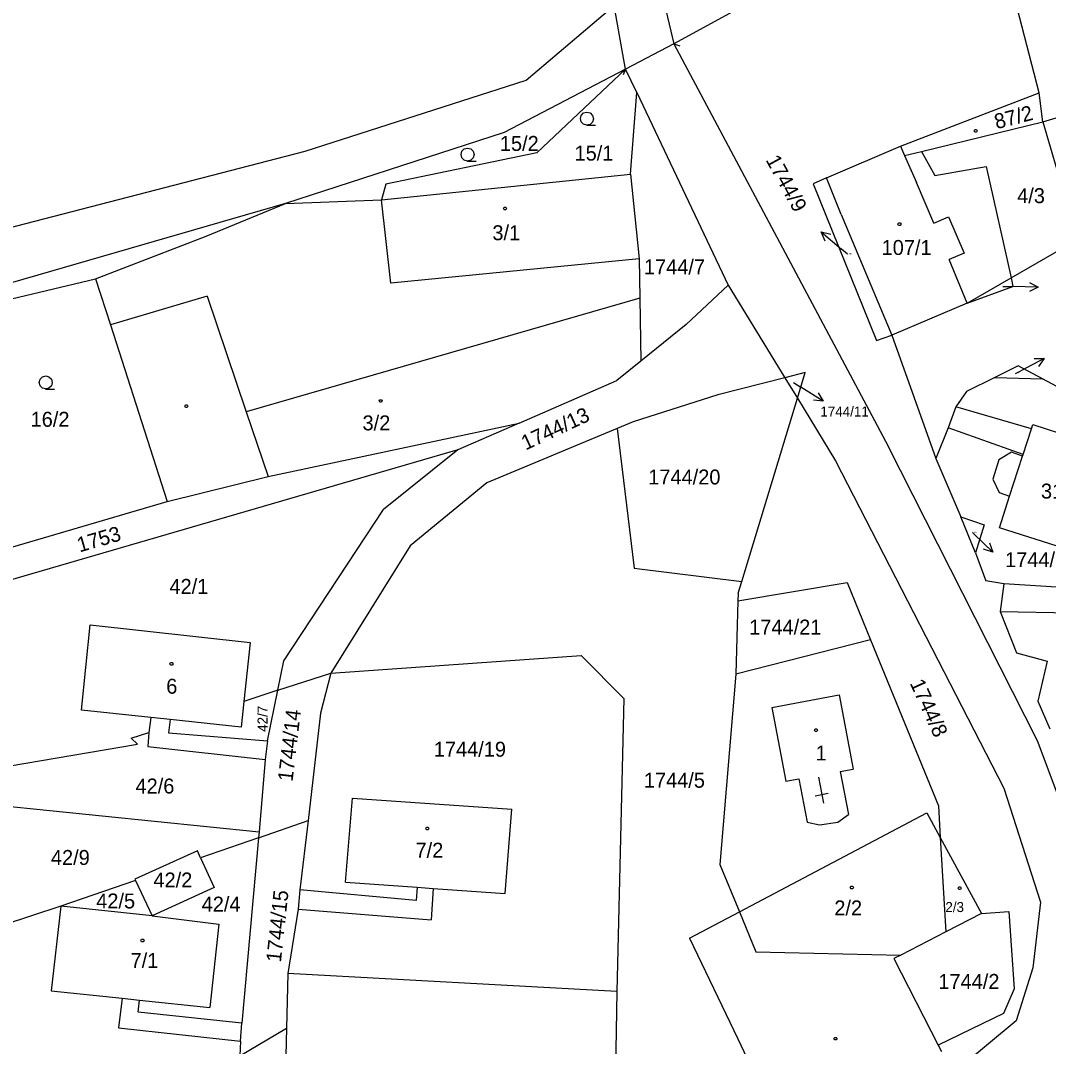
# Model space of a CAD drawing. Extents: x -799786 to -795190, y -1021716 to -1017834.
# Drawn here: x -798047.9 to -797930.9, y -1019053.9 to -1018937.1 of the extents above; entities that cross this region are included whole.
import ezdxf

# ---------------------------------------------------------------- set-up
doc = ezdxf.new("R2010")
doc.units = 0
for name, color, linetype in [('Default', 7, 'Continuous'), ('KN_HRANICE', 7, 'Continuous'), ('KN_KULTURY', 7, 'Continuous'), ('KN_PARCELY', 7, 'Continuous'), ('KN_SLUCKY', 7, 'Continuous')]:
    doc.layers.add(name, color=color, linetype=linetype)

# ---------------------------------------------------------------- blocks, each defined once
blk = doc.blocks.new('304')
at = {"layer": 'Default'}
blk.add_lwpolyline([(0, 0), (-0.38, 0.1), (-0.65, 0.37), (-0.75, 0.74), (-0.65, 1.11), (-0.38, 1.38), (-0.01, 1.48), (0.36, 1.38), (0.63, 1.11), (0.73, 0.73), (0.63, 0.35), (0.36, 0.08), (-0.02, -0.02), (0.98, -0.02)], dxfattribs=at)
blk = doc.blocks.new('NAHRADNI_SYMBOL')
at = {"layer": 'Default'}
blk.add_lwpolyline([(0.09, 0.15), (0.18, 0), (0.09, -0.15), (-0.09, -0.15), (-0.18, 0), (-0.09, 0.15), (0.09, 0.15)], dxfattribs=at)
blk = doc.blocks.new('10292')
at = {"layer": 'Default'}
blk.add_line((0, 3), (0, 0), dxfattribs=at)
blk.add_lwpolyline([(-0.5, 2), (0, 3), (0.5, 2)], dxfattribs=at)
blk = doc.blocks.new('402')
at = {"layer": 'Default'}
blk.add_lwpolyline([(0.09, 0.15), (0.18, 0), (0.09, -0.15), (-0.09, -0.15), (-0.18, 0), (-0.09, 0.15), (0.09, 0.15)], dxfattribs=at)
blk = doc.blocks.new('4091')
at = {"layer": 'Default'}
for p, q in [((0, 0), (0, 3)), ((0.75, 2), (-0.75, 2))]:
    blk.add_line(p, q, dxfattribs=at)
blk = doc.blocks.new('4201')
at = {"layer": 'Default'}
blk.add_line((0, 0), (-0.5, -0.5), dxfattribs=at)

msp = doc.modelspace()

# ---------------------------------------------------------------- linework, layer by layer
at = {"layer": 'KN_HRANICE'}
for p, q in [((-797931.93, -1018945.35), (-797936.24, -1018928.69)), ((-797959.42, -1018932.05), (-797973.52, -1018939.78)), ((-797990.31, -1018943.91), (-797980.3, -1018935.41)), ((-797979.01, -1018942.65), (-797980.3, -1018935.41)), ((-797973.52, -1018939.78), (-797979.01, -1018942.65)), ((-797973.52, -1018939.78), (-797949.14, -1018985.55)), ((-797979.01, -1018942.65), (-797992.83, -1018949.87)), ((-797979.01, -1018942.65), (-797989.12, -1018952.16)), ((-797977.72, -1018945.29), (-797979.01, -1018942.65)), ((-798015.47, -1018951.99), (-797990.31, -1018943.91)), ((-797978.44, -1018954.61), (-797977.72, -1018945.29)), ((-797977.72, -1018945.29), (-797967.32, -1018967.21)), ((-797947.72, -1018951.42), (-797931.93, -1018945.35)), ((-797931.53, -1018948.65), (-797931.93, -1018945.35)), ((-797945.33, -1018952), (-797931.53, -1018948.65)), ((-797931.53, -1018948.65), (-797928.55, -1018958.72)), ((-797992.83, -1018949.87), (-798017.72, -1018957.95)), ((-797956.16, -1018955.02), (-797947.72, -1018951.42)), ((-797947.72, -1018951.42), (-797947.25, -1018952.46)), ((-798092.87, -1018972.02), (-798015.47, -1018951.99)), ((-797989.12, -1018952.16), (-798006.31, -1018955.72)), ((-797947.25, -1018952.46), (-797945.33, -1018952)), ((-797945.33, -1018952), (-797943.82, -1018954.73)), ((-797943.82, -1018954.73), (-797937.95, -1018953.73)), ((-797937.95, -1018953.73), (-797935.14, -1018966.41)), ((-798006.8, -1018957.51), (-797978.44, -1018954.61)), ((-797978.44, -1018954.61), (-797977.47, -1018964.22)), ((-797956.16, -1018955.02), (-797957.66, -1018955.7)), ((-797954.48, -1018959.19), (-797956.16, -1018955.02)), ((-798006.31, -1018955.72), (-798006.8, -1018957.51)), ((-797957.66, -1018955.7), (-797950.45, -1018973.51)), ((-798017.72, -1018957.95), (-798093.97, -1018979.94)), ((-798026.73, -1018961.66), (-798017.72, -1018957.95)), ((-798017.72, -1018957.95), (-798006.8, -1018957.51)), ((-797954.48, -1018959.19), (-797948.7, -1018972.9)), ((-798039.33, -1018966.51), (-798026.73, -1018961.66)), ((-797935.14, -1018966.41), (-797927.62, -1018962.07)), ((-797977.47, -1018964.22), (-797977.39, -1018968.72)), ((-798055.93, -1018970.44), (-798039.33, -1018966.51)), ((-798039.33, -1018966.51), (-798037.65, -1018971.74)), ((-797940.13, -1018969.29), (-797935.14, -1018966.41)), ((-797935.14, -1018966.41), (-797934.92, -1018967.39)), ((-797967.32, -1018967.21), (-797972.13, -1018971.71)), ((-797967.32, -1018967.21), (-797960.88, -1018977.77)), ((-797940.13, -1018969.29), (-797934.92, -1018967.39)), ((-797977.39, -1018968.72), (-798022.18, -1018981.64)), ((-797977.39, -1018968.72), (-797977.26, -1018975.87)), ((-797940.13, -1018969.29), (-797948.7, -1018972.9)), ((-798037.65, -1018971.74), (-798031.19, -1018991.85)), ((-797972.13, -1018971.71), (-797977.26, -1018975.87)), ((-797950.45, -1018973.51), (-797948.7, -1018972.9)), ((-797948.7, -1018972.9), (-797943.7, -1018986.95)), ((-797977.26, -1018975.87), (-797979.99, -1018978.08)), ((-797958.57, -1018977.18), (-797960.88, -1018977.77)), ((-797959.46, -1018980.1), (-797958.57, -1018977.18)), ((-797934.34, -1018976.4), (-797936.98, -1018977.73)), ((-797931.55, -1018977.89), (-797934.34, -1018976.4)), ((-797991.11, -1018982.92), (-797979.99, -1018978.08)), ((-797960.88, -1018977.77), (-797968.5, -1018979.72)), ((-797960.88, -1018977.77), (-797959.46, -1018980.1)), ((-797936.98, -1018977.73), (-797940.19, -1018979.34)), ((-797936.98, -1018977.73), (-797931.55, -1018977.89)), ((-797925.6, -1018981.08), (-797931.55, -1018977.89)), ((-797940.19, -1018979.34), (-797941.42, -1018981.08)), ((-797968.5, -1018979.72), (-797978.16, -1018982.8)), ((-797965.79, -1019000.95), (-797959.46, -1018980.1)), ((-797959.46, -1018980.1), (-797955.12, -1018987.21)), ((-798022.18, -1018981.64), (-798019.7, -1018989)), ((-797941.42, -1018981.08), (-797942.31, -1018983.45)), ((-797932.82, -1018983.58), (-797941.42, -1018981.08)), ((-798019.7, -1018989), (-797991.11, -1018982.92)), ((-797991.11, -1018982.92), (-797998.12, -1018985.97)), ((-797978.16, -1018982.8), (-797979.95, -1018983.55)), ((-797932.82, -1018983.58), (-797932.67, -1018983.1)), ((-797932.67, -1018983.1), (-797924.31, -1018985.78)), ((-797979.95, -1018983.55), (-797994.81, -1018989.72)), ((-797942.31, -1018983.45), (-797943.7, -1018986.95)), ((-797933.76, -1018986.48), (-797942.31, -1018983.45)), ((-797998.12, -1018985.97), (-798052.33, -1019001.73)), ((-797998.12, -1018985.97), (-798006.58, -1018992.76)), ((-797932.14, -1019019.09), (-797949.14, -1018985.55)), ((-797935.1, -1018986.25), (-797936.51, -1018987.12)), ((-797933.84, -1018986.67), (-797935.1, -1018986.25)), ((-797933.84, -1018986.67), (-797933.76, -1018986.48)), ((-797955.12, -1018987.21), (-797935.97, -1019024.47)), ((-797943.7, -1018986.95), (-797940.85, -1018993.6)), ((-797936.51, -1018987.12), (-797937.21, -1018989.3)), ((-798031.19, -1018991.85), (-798019.7, -1018989)), ((-797994.81, -1018989.72), (-798003.54, -1018996.9)), ((-797937.21, -1018989.3), (-797936.5, -1018990.81)), ((-797936.5, -1018990.81), (-797935.31, -1018991.23)), ((-797936.46, -1018994.83), (-797935.31, -1018991.23)), ((-798048.75, -1018997.01), (-798031.19, -1018991.85)), ((-798017.9, -1019009.97), (-798006.58, -1018992.76)), ((-797940.85, -1018993.6), (-797938.18, -1018994.51)), ((-797939.19, -1018997.69), (-797940.85, -1018993.6)), ((-797938.18, -1018994.51), (-797939.19, -1018997.69)), ((-797927.99, -1018997.54), (-797936.46, -1018994.83)), ((-798003.54, -1018996.9), (-798012.54, -1019011.37)), ((-797939.19, -1018997.69), (-797938.02, -1019000.87)), ((-797966.22, -1019003.16), (-797953.79, -1019001.07)), ((-797966.19, -1019002.29), (-797965.79, -1019000.95)), ((-797953.79, -1019001.07), (-797951.13, -1019007.59)), ((-797935.97, -1019001.2), (-797938.02, -1019000.87)), ((-797935.97, -1019001.2), (-797936.37, -1019004.37)), ((-797929.37, -1019001.64), (-797935.97, -1019001.2)), ((-797966.19, -1019002.29), (-797966.22, -1019003.16)), ((-797966.22, -1019003.16), (-797966.46, -1019011.5)), ((-797936.37, -1019004.37), (-797934.5, -1019009.07)), ((-797936.37, -1019004.37), (-797924.56, -1019004.56)), ((-798040.93, -1019015.59), (-798039.96, -1019005.89)), ((-798039.96, -1019005.89), (-798021.74, -1019007.89)), ((-797951.13, -1019007.59), (-797966.46, -1019011.5)), ((-797951.13, -1019007.59), (-797943.41, -1019026.48)), ((-798021.74, -1019007.89), (-798022.45, -1019014.59)), ((-798018.58, -1019013.33), (-798017.9, -1019009.97)), ((-797934.5, -1019009.07), (-797931.02, -1019010.03)), ((-797931.02, -1019010.03), (-797932.1, -1019014.57)), ((-798018.58, -1019013.33), (-798012.54, -1019011.37)), ((-798012.54, -1019011.37), (-798013.74, -1019015.95)), ((-797966.46, -1019011.5), (-797968.29, -1019033.16)), ((-798018.58, -1019013.33), (-798022.45, -1019014.59)), ((-798019.78, -1019019.07), (-798018.58, -1019013.33)), ((-798022.45, -1019014.59), (-798022.77, -1019017.53)), ((-797932.1, -1019014.57), (-797930.74, -1019017.71)), ((-798033.05, -1019016.43), (-798040.93, -1019015.59)), ((-798033.05, -1019016.43), (-798033.26, -1019018.12)), ((-798030.86, -1019016.67), (-798031.02, -1019018.16)), ((-798022.77, -1019017.53), (-798030.86, -1019016.67)), ((-798013.74, -1019015.95), (-798015.12, -1019028.17)), ((-798035.29, -1019018.8), (-798033.26, -1019018.12)), ((-798033.26, -1019018.12), (-798033.4, -1019019.72)), ((-798031.02, -1019018.16), (-798019.78, -1019019.07)), ((-798034.55, -1019019.48), (-798035.29, -1019018.8)), ((-798019.78, -1019019.07), (-798020.04, -1019021.21)), ((-797929.89, -1019025.05), (-797932.14, -1019019.09)), ((-798049.27, -1019021.96), (-798034.55, -1019019.48)), ((-798033.4, -1019019.72), (-798020.04, -1019021.21)), ((-798020.04, -1019021.21), (-798020.73, -1019029.44)), ((-797935.97, -1019024.47), (-797931.77, -1019037.45)), ((-798051.89, -1019026.25), (-798020.73, -1019029.44)), ((-798010.88, -1019035.18), (-798010.11, -1019025.6)), ((-798010.11, -1019025.6), (-797991.95, -1019026.87)), ((-797992.72, -1019036.45), (-797991.95, -1019026.87)), ((-797966.06, -1019038.55), (-797944.73, -1019027.27)), ((-797944.73, -1019027.27), (-797943.2, -1019030.09)), ((-797943.41, -1019026.48), (-797943.2, -1019030.09)), ((-798020.79, -1019030.13), (-798015.12, -1019028.17)), ((-798015.12, -1019028.17), (-798016.07, -1019036.05)), ((-798020.73, -1019029.44), (-798020.79, -1019030.13)), ((-798020.79, -1019030.13), (-798027.38, -1019032.41)), ((-798020.79, -1019030.13), (-798022.68, -1019051.2)), ((-797943.2, -1019030.09), (-797938.51, -1019038.74)), ((-797943.2, -1019030.09), (-797942.57, -1019040.83)), ((-798027.75, -1019031.59), (-798034.86, -1019034.83)), ((-798027.38, -1019032.41), (-798027.75, -1019031.59)), ((-798027.38, -1019032.41), (-798025.84, -1019035.76)), ((-797968.29, -1019033.16), (-797966.06, -1019038.55)), ((-798034.79, -1019034.97), (-798043.3, -1019037.91)), ((-798034.86, -1019034.83), (-798034.79, -1019034.97)), ((-798034.79, -1019034.97), (-798032.91, -1019039)), ((-798025.84, -1019035.76), (-798032.91, -1019039)), ((-798010.88, -1019035.18), (-798002.75, -1019035.75)), ((-798002.75, -1019035.75), (-798002.85, -1019037.24)), ((-798016.07, -1019036.05), (-798016.28, -1019038.23)), ((-798002.85, -1019037.24), (-798016.07, -1019036.05)), ((-798000.9, -1019035.88), (-798001.14, -1019039.44)), ((-798000.9, -1019035.88), (-797992.72, -1019036.45)), ((-798043.3, -1019037.91), (-798049.84, -1019040.07)), ((-798043.3, -1019037.91), (-798044.39, -1019047.52)), ((-798032.91, -1019039), (-798043.3, -1019037.91)), ((-797931.77, -1019037.45), (-797932.64, -1019044.93)), ((-798032.91, -1019039), (-798025.3, -1019039.94)), ((-798016.28, -1019038.23), (-798017.45, -1019045.58)), ((-798016.28, -1019038.23), (-798001.14, -1019039.44)), ((-797971.73, -1019041.54), (-797966.06, -1019038.55)), ((-797966.06, -1019038.55), (-797964.19, -1019043.08)), ((-797938.51, -1019038.74), (-797942.57, -1019040.83)), ((-797938.51, -1019038.74), (-797935.38, -1019038.51)), ((-797935.38, -1019038.51), (-797934.78, -1019047.32)), ((-798025.3, -1019039.94), (-798026.34, -1019049.44)), ((-797971.73, -1019041.54), (-797966.24, -1019053)), ((-797942.57, -1019040.83), (-797947.69, -1019043.46)), ((-797964.19, -1019043.08), (-797947.69, -1019043.46)), ((-797947.69, -1019043.46), (-797948.49, -1019043.87)), ((-797948.49, -1019043.87), (-797943.44, -1019053.71)), ((-797932.64, -1019044.93), (-797934.54, -1019050.94)), ((-798017.45, -1019045.58), (-798017.6, -1019051.79)), ((-797979.99, -1019047.61), (-798017.45, -1019045.58)), ((-798044.39, -1019047.52), (-798036.3, -1019048.36)), ((-797934.78, -1019047.32), (-797935.98, -1019050.1)), ((-798036.3, -1019048.36), (-798036.71, -1019051.75)), ((-798034.47, -1019049.96), (-798034.32, -1019048.58)), ((-798034.32, -1019048.58), (-798026.34, -1019049.44)), ((-797979.99, -1019047.61), (-797980.56, -1019076.83)), ((-798022.68, -1019051.2), (-798034.47, -1019049.96)), ((-797935.98, -1019050.1), (-797943.44, -1019053.71)), ((-797934.54, -1019050.94), (-797940.64, -1019055.99)), ((-798036.71, -1019051.75), (-798022.83, -1019053.26)), ((-798022.92, -1019054.93), (-798017.6, -1019051.79)), ((-798022.83, -1019053.26), (-798022.68, -1019051.2)), ((-798017.6, -1019051.79), (-798017.86, -1019062.37)), ((-798022.83, -1019053.26), (-798022.92, -1019054.93)), ((-797966.24, -1019053), (-797963.7, -1019058.32)), ((-797943.44, -1019053.71), (-797943.07, -1019054.43))]:
    msp.add_line(p, q, dxfattribs=at)
for points in [[(-797979.95, -1018983.55), (-797978.04, -1018999.42), (-797965.79, -1019000.95)], [(-798012.54, -1019011.37), (-797984.07, -1019009.38), (-797979.22, -1019014.26), (-797979.99, -1019047.61)]]:
    msp.add_lwpolyline(points, dxfattribs=at)
at = {"layer": 'KN_PARCELY'}
for p, q in [((-797953.75, -1018963.71), (-797954.45, -1018963.12)), ((-797936.06, -1018967.37), (-797935.04, -1018967.39)), ((-797934.64, -1018977.28), (-797934.03, -1018976.96)), ((-797959.91, -1018978.3), (-797959.06, -1018978.83)), ((-797939.52, -1018995.38), (-797939.36, -1018995.53))]:
    msp.add_line(p, q, dxfattribs=at)
at = {"layer": 'KN_SLUCKY'}
for p, q in [((-797975.25, -1018932.49), (-797973.52, -1018939.78)), ((-797931.53, -1018948.65), (-797920.53, -1018945.32)), ((-797947.25, -1018952.46), (-797945.89, -1018955.56)), ((-797943.94, -1018960.16), (-797945.89, -1018955.56)), ((-798005.74, -1018967.01), (-798006.8, -1018957.51)), ((-797943.94, -1018960.16), (-797942.25, -1018959.45)), ((-797942.25, -1018959.45), (-797940.49, -1018963.6)), ((-797977.47, -1018964.22), (-798005.74, -1018967.01)), ((-797940.49, -1018963.6), (-797942.18, -1018964.3)), ((-797940.13, -1018969.29), (-797942.18, -1018964.3)), ((-798026.62, -1018968.47), (-798037.65, -1018971.74)), ((-798026.62, -1018968.47), (-798022.18, -1018981.64)), ((-797933.76, -1018986.48), (-797932.82, -1018983.58)), ((-797935.31, -1018991.23), (-797933.84, -1018986.67)), ((-797962.37, -1019015.29), (-797954.7, -1019013.85)), ((-797954.7, -1019013.85), (-797953.1, -1019022.31)), ((-797962.37, -1019015.29), (-797960.77, -1019023.67)), ((-798030.86, -1019016.67), (-798033.05, -1019016.43)), ((-797954.58, -1019022.57), (-797953.1, -1019022.31)), ((-797954.58, -1019022.57), (-797953.62, -1019027.48)), ((-797960.77, -1019023.67), (-797959.29, -1019023.41)), ((-797959.29, -1019023.41), (-797958.33, -1019028.34)), ((-797954.85, -1019028.34), (-797953.62, -1019027.48)), ((-797958.33, -1019028.34), (-797956.95, -1019028.63)), ((-797956.95, -1019028.63), (-797954.85, -1019028.34)), ((-798002.75, -1019035.75), (-798000.9, -1019035.88)), ((-798036.3, -1019048.36), (-798034.32, -1019048.58))]:
    msp.add_line(p, q, dxfattribs=at)

# ---------------------------------------------------------------- block references
at = {"layer": 'KN_KULTURY'}
for name, p in [('304', (-797983.41, -1018949.01)), ('NAHRADNI_SYMBOL', (-797939.17, -1018949.68)), ('304', (-797996.99, -1018953.1)), ('402', (-797992.73, -1018958.51)), ('402', (-797947.84, -1018960.29)), ('304', (-798045, -1018979.04)), ('NAHRADNI_SYMBOL', (-798006.88, -1018980.41)), ('402', (-798029.01, -1018981.01)), ('402', (-798030.7, -1019010.33)), ('402', (-797957.33, -1019017.87)), ('402', (-798001.57, -1019029.06)), ('402', (-797953.25, -1019035.77)), ('402', (-797940.98, -1019035.86)), ('402', (-798034, -1019041.8)), ('402', (-797955.12, -1019052.98))]:
    msp.add_blockref(name, p, dxfattribs=at)
at = {"layer": 'KN_KULTURY', "rotation": -169.03316700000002}
msp.add_blockref('4091', (-797957.07, -1019023.22), dxfattribs=at)
at = {"layer": 'KN_PARCELY'}
for p, rotation in [((-797954.45, -1018963.12), 49.56084899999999), ((-797935.04, -1018967.39), -91.16820300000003), ((-797934.03, -1018976.96), -62.176538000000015), ((-797959.06, -1018978.83), -122.16521900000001), ((-797939.36, -1018995.53), -134.14003700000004)]:
    msp.add_blockref('10292', p, dxfattribs=dict(at, rotation=rotation))
at = {"layer": 'KN_SLUCKY'}
for p, rotation in [((-797973.52, -1018939.78), 117.16986899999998), ((-797979.01, -1018942.65), 22.746423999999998)]:
    msp.add_blockref('4201', p, dxfattribs=dict(at, rotation=rotation))

# ---------------------------------------------------------------- texts
at = {"layer": 'KN_PARCELY'}
for s, height, rotation, p in [('87/2', 1.7, 14.439, (-797936.79, -1018949.48)), ('1744/9', 1.7, 298.568, (-797963.1, -1018952.97)), ('1744/13', 1.7, 24.924, (-797990.39, -1018986.05)), ('1753', 1.7, 16.215, (-798041.16, -1018997.65)), ('1744/8', 1.7, 294.386, (-797946.69, -1019012.51)), ('42/7', 1.14, 90.012, (-798019.76, -1019018.06)), ('1744/14', 1.7, 83.251, (-798016.92, -1019023.78)), ('1744/15', 1.7, 83.881, (-798018.24, -1019044.34))]:
    msp.add_text(s, height=height, rotation=rotation, dxfattribs=at).set_placement(p)
for s, height, p in [('15/2', 1.7, (-797993.32, -1018951.95)), ('15/1', 1.7, (-797984.82, -1018953.05)), ('4/3', 1.7, (-797934.44, -1018957.89)), ('3/1', 1.7, (-797994.17, -1018962.11)), ('107/1', 1.7, (-797949.87, -1018963.79)), ('1744/7', 1.7, (-797976.92, -1018965.99)), ('1744/9', 0.1, (-797953.73, -1018963.71)), ('107/2', 0.1, (-797936.04, -1018967.37)), ('1818/2', 0.1, (-797934.62, -1018977.28)), ('1744/11', 0.1, (-797959.89, -1018978.3)), ('16/2', 1.7, (-798046.73, -1018983.34)), ('3/2', 1.7, (-798008.95, -1018983.75)), ('1744/11', 1.14, (-797956.84, -1018982.18)), ('1744/20', 1.7, (-797976.43, -1018989.91)), ('31/3', 1.7, (-797931.73, -1018991.51)), ('1744/10', 0.1, (-797939.5, -1018995.38)), ('1744/10', 1.7, (-797935.82, -1018999.32)), ('42/1', 1.7, (-798030.93, -1019002.36)), ('1744/21', 1.7, (-797964.94, -1019006.99)), ('6', 1.7, (-798031.29, -1019013.72)), ('1744/19', 1.7, (-798000.84, -1019020.89)), ('1', 1.7, (-797957.38, -1019021.32)), ('1744/5', 1.7, (-797976.93, -1019024.42)), ('42/6', 1.7, (-798034.79, -1019025.08)), ('7/2', 1.7, (-798002.92, -1019032.38)), ('42/9', 1.7, (-798044.42, -1019033.21)), ('42/2', 1.7, (-798032.75, -1019035.77)), ('42/5', 1.7, (-798039.26, -1019038.16)), ('42/4', 1.7, (-798027.26, -1019038.52)), ('2/2', 1.7, (-797955.25, -1019038.95)), ('2/3', 1.14, (-797942.61, -1019038.57)), ('7/1', 1.7, (-798035.35, -1019044.93)), ('1744/2', 1.7, (-797943.41, -1019047.32))]:
    msp.add_text(s, height=height, dxfattribs=at).set_placement(p)

doc.saveas('drawing.dxf')
